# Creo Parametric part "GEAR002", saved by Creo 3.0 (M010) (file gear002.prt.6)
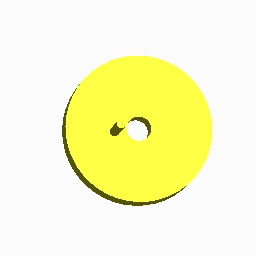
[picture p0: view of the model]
Units: millimeter Newton Second (mmNs); MM, TONNE, SECS

Created from: INLBS_PART_SOLID.PRT

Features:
  1. datum plane "RIGHT"
  2. datum plane "TOP"
  3. datum plane "FRONT"
  4. coordinate system
  5. extrusion "Extrude 1"
  6. extrusion "Extrude 2"

Surfaces: 6 plane, 6 cylinder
